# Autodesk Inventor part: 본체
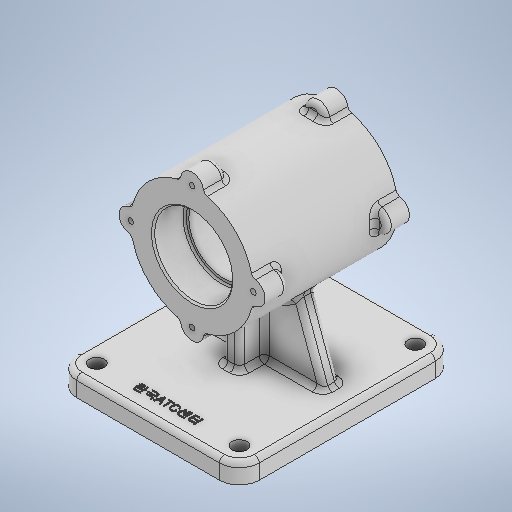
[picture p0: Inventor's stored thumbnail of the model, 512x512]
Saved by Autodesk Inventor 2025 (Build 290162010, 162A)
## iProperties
Created: 2024-08
Part Number: 본체
Material: 일반
Document SubType Name: Modeling
Designer: 학생
Density: 1 g/cm^3
Appearance: 기본값
Mass: 450.142 g
Surface Area: 796.85 cm^2
Volume: 450.142 cm^3
Author: 학생
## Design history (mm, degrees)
sketch "스케치1"
  geometry: L1 (55, 70)-(-55, 70); L2 (-55, 70)-(-55, -60); L3 (-55, -60)-(55, -60); L4 (55, -60)-(55, 70); L5 (0, 0)-(0, -7.399); L6 (0, 0)-(6.141, 0)
  constraints: 12 end point, 2 horizontal, 2 parallel, 1 perpendicular, 1 vertical, 1 other
  dimensions: "d0" = 130 distance of L3.end L1.start; "d1" = 110 distance of L2.end L3.end; "d12" = 70 distance from line of L1 L5.start
extrude "돌출1" new body sketch "스케치1" distance "d2" = 12; taper "d3" = 0 deg
fillet "모깎기1" dims "d4" = 12
sketch "스케치2" dims "d5" = 74
  geometry: L1 (-43, 0)-(43, 0) reference; C1 r 7 at (0, 119); C2 r 7 at (-37, 82); C3 r 7 at (0, 45); C4 r 7 at (37, 82); 12 further points
  constraints: 4 centre point, 2 midpoint, 2 vertical alignment, 12 other
  dimensions: "d6" = 82 distance of point (0, 0) point (0, 82); "d7" = 14 diameter of C1; "d10" = 360 deg dimension on point (0, 82) C1.centre (derived)
  node "스케치 - 원형 패턴1" dims "d10" = 360 deg (derived)
extrude "돌출2" join sketch "스케치2" stored distance "d13" = 87; taper "d14" = 0 deg
extrude "돌출3" cut sketch "스케치2" stored distance "d15" = 59; taper "d16" = 0 deg
sketch "스케치3"
  geometry: L1 (-2, 20)-(2, 20); L2 (5, 17)-(5, -17); L3 (2, -20)-(-2, -20); L4 (-5, -17)-(-5, 17); L5 (-43, 0)-(43, 0) reference; L6 (0, 0)-(0, 6.072); A1 r 3 centre (2, 17) between (5, 17) and (2, 20); A2 r 3 centre (-2, 17) between (-2, 20) and (-5, 17); A3 r 3 centre (-2, -17) between (-5, -17) and (-2, -20); A4 r 3 centre (2, -17) between (2, -20) and (5, -17); 3 further points
  constraints: 10 end point, 8 point on circle, 8 tangent, 6 point on line, 4 centre point, 3 equal radius, 2 parallel, 1 horizontal, 1 perpendicular, 1 vertical, 2 other
  dimensions: "d17" = 10 distance of point (-5, 20) point (5, 20); "d18" = 40 distance of point (-5, -20) point (-5, 20); "d19" = 3 radius of A1
extrude "돌출4" join sketch "스케치3" stored distance "d20" = 59; taper "d21" = 0 deg
sketch "스케치4"
  geometry: L1 (-41, 5)-(41, 5); L2 (41, 5)-(41, -5); L3 (41, -5)-(-41, -5); L4 (-41, -5)-(-41, 5); L5 (0, 0)-(0, 9.752); L6 (-43, 0)-(43, 0) reference
  constraints: 10 end point, 2 parallel, 1 horizontal, 1 perpendicular, 1 vertical, 2 other
  dimensions: "d22" = 10 distance of L3.end L1.start; "d23" = 82 distance of L2.end L3.end
extrude "돌출5" join sketch "스케치4" distance "d24" = 60; taper "d25" = 0 deg
feature "면 기울기1" dims angle "d26" = 20 deg
feature "면 기울기2" dims angle "d27" = 20 deg
sketch "스케치5"
  geometry: L1 (89, 43.5)-(75, 43.5) reference; L2 (82, 43.5)-(82, -43.5); L3 (75, -43.5)-(89, -43.5) reference; L4 (82, 43.5)-(105.5, 43.5); L5 (105.5, 43.5)-(105.5, 24.5); L6 (105.5, 24.5)-(103, 24.5); L7 (103, 24.5)-(103, -24.5); L8 (103, -24.5)-(105.5, -24.5); L9 (105.5, -24.5)-(105.5, -43.5); L10 (105.5, -43.5)-(82, -43.5); 7 further points
  constraints: 16 end point, 4 perpendicular, 2 equal length, 2 horizontal, 2 midpoint, 1 collinear
  dimensions: "d28" = 19 distance of L4.end L5.end; "d29" = 23.5 distance of L2.start L4.end; "d30" = 21 distance between parallel lines of L2 L7
revolve "회전1" sketch "스케치5" stored, may be unused: angle "d31" = 90 deg
sketch "스케치6"
  geometry: 2 further points
  constraints: 1 vertical alignment, 1 other
  dimensions: "d32" = 58 distance of point (0, -58) point (0, 0)
feature "엠보싱1" sketch "스케치6" dims "d0" = 130, "d1" = 110, "d12" = 70, "d33" = 0.5, "d34" = 0
chamfer "모따기1" distance "d35" = 1; stored, may be unused: second distance "d36" = 2, angle "d37" = 45 deg
fillet "모깎기2" dims "d38" = 1
fillet "모깎기3" dims "d39" = 1
fillet "모깎기4" dims "d40" = 3
fillet "모깎기5" dims "d41" = 3
fillet "모깎기6" dims "d42" = 3
fillet "모깎기7" dims "d43" = 3
sketch "스케치7"
  geometry: L1 (-43, -70)-(43, -70) reference; L2 (-55, 48)-(-55, -58) reference; 2 further points
  dimensions: "d47" = 12 distance from line of L1 point (-43, -58); "d48" = 12 distance from line of L2 point (-43, -58)
hole "구멍1" sketch "스케치7" at (-43, -58) diameter "d49" = 9; stored, may be unused: countersink angle "d53" = 90 deg, drill point angle "d55" = 0 deg; dims "d50" = 6, "d51" = 14, "d52" = 19, "d54" = 12
node "작업 평면1"
sketch "스케치8"
  geometry: C1 r 24.5 at (0, 82) reference; A1 r 37 centre (0, 82) between (-9.104, 117.863) and (-35.862, 91.104) reference; A2 r 3 centre (-38.77, 91.842) between (-38.239, 88.889) and (-35.862, 91.104) reference; A3 r 7 centre (-37, 82) between (-38.239, 88.889) and (-38.239, 75.111) reference; A4 r 3 centre (-38.77, 72.158) between (-35.862, 72.896) and (-38.239, 75.111) reference; A5 r 37 centre (0, 82) between (-35.862, 72.896) and (-9.104, 46.138) reference; A6 r 3 centre (-9.842, 43.23) between (-6.889, 43.761) and (-9.104, 46.138) reference; A7 r 7 centre (0, 45) between (-6.889, 43.761) and (6.889, 43.761) reference; A8 r 3 centre (9.842, 43.23) between (9.104, 46.138) and (6.889, 43.761) reference; A9 r 37 centre (0, 82) between (9.104, 46.138) and (35.863, 72.896) reference; A10 r 3 centre (38.77, 72.158) between (38.239, 75.111) and (35.863, 72.896) reference; A11 r 7 centre (37, 82) between (38.239, 75.111) and (38.239, 88.889) reference; A12 r 3 centre (38.77, 91.842) between (35.863, 91.104) and (38.239, 88.889) reference; A13 r 37 centre (0, 82) between (35.863, 91.104) and (9.104, 117.863) reference; A14 r 3 centre (9.842, 120.77) between (6.889, 120.239) and (9.104, 117.863) reference; A15 r 7 centre (0, 119) between (6.889, 120.239) and (-6.889, 120.239) reference; A16 r 3 centre (-9.842, 120.77) between (-9.104, 117.863) and (-6.889, 120.239) reference; 5 further points
  constraints: 4 coincident
hole "구멍2" sketch "스케치8" at (0, 119), (37, 82), (-37, 82), (0, 45) diameter "d57" = 3.242; stored, may be unused: countersink angle "d61" = 90 deg, drill point angle "d63" = 118 deg; dims "d58" = 8, "d59" = 4, "d60" = 2, "d62" = 10
node "작업 평면2"
fillet "모깎기8" dims "d64" = 3
fillet "모깎기9" dims "d65" = 3
sketch "스케치9"
  geometry: L1 (55, -58)-(55, 48) reference; L2 (55, 0)-(55, 14); L3 (55.304, 0)-(41.304, 0); L4 (-55, 48)-(-55, -58) reference; L5 (-55, 0)-(-55, -14); L6 (-55, 0)-(-41, 0); 1 further point
  constraints: 8 end point, 4 point on line, 2 horizontal
  dimensions: "d67" = 14 distance of L3.start L3.end; "d70" = 14 distance of L5.start L6.end
node "솔리드1"
pattern_circular "원형 패턴1" dims "d45" = 360 deg
mirror "미러1"
mirror "미러2"
mirror "미러3"
node "투영된 루프1"
feature "A9D066F2-1C7D-4E18-AEED-F7BC21143FA4" dims "d49" = 9, "d50" = 6, "d51" = 14, "d52" = 19, "d53" = 90 deg, "d54" = 12, "d55" = 0
